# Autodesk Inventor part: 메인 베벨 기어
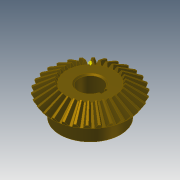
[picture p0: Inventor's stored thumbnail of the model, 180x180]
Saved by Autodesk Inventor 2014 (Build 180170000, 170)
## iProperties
Created: 2014-10
Part Number: 메인 베벨 기어
Material: 강철
Document SubType Name: Modeling
Designer: KYOUNG IL JANG
Categories: <?xml version="1.0" encoding="UTF-16"?> <MemberInstance><Categories><FamilyTemplate><FamilyTemplateParameter ValueType="xs:double" Id="1" ObjectReferenceKey="da
Mass: 269.24 g
Surface Area: 108.837 cm^2
Volume: 34.2981 cm^3
Density: 7.85 g/cm^3
Appearance: Brindle
CustomPartVersion: 1
Company: 한국ATC센터
Author: KYOUNG IL JANG
Revision Number: 1
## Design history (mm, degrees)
node "맨 위 점"
node "메쉬 평면2"
sketch "톱니 본체 스케치"
  geometry: L1 (0, 0)-(28.669, -21.997); L2 (28.669, -21.997)-(31.109, -18.336); L3 (31.109, -18.336)-(0, 0); L4 (30, -20)-(0, 0); L5 (17.219, -13.212)-(18.685, -11.013); L6 (28.669, -21.997)-(17.219, -13.212); L7 (31.109, -18.336)-(18.685, -11.013); L8 (0, -39.387)-(0, 6.564) reference; L9 (0, -20)-(31.109, -20)
  constraints: 16 end point, 4 point on line, 3 perpendicular, 2 collinear, 1 horizontal alignment, 1 vertical alignment
  dimensions: "d0" = 60 diameter of L4.start L8 (= da_de); "d1" = 57.33744 diameter of L1.end L8 (= da_dfe); "d2" = 62.2188 diameter of L2.end L8 (= da_dae); "d3" = 14.4 distance between parallel lines of L2 L5 (= da_b); "d4" = 18.3359 vertical distance of L2.end L1.start (= da_ve)
revolve "톱니 본체" sketch "톱니 본체 스케치" stored, may be unused: angle "d5" = 90 deg
node "시작점"
node "톱니 평면"
sketch "시작 스케치"
  geometry: L1 (0, -23.505)-(0, 10.645) reference; L2 (-0.709, -2.928)-(0.709, -2.928); A1 r 19.188 centre (-19.457, -7.014) between (-0.709, -2.928) and (-3.232, 3.229); A2 r 19.188 centre (19.457, -7.014) between (3.232, 3.229) and (0.709, -2.928); A3 r 57.403 centre (0, -54.083) between (3.232, 3.229) and (-3.232, 3.229); 1 further point
  constraints: 6 point on circle, 3 centre point, 3 symmetric about line, 2 end point, 1 coincident, 1 perpendicular, 1 other
  dimensions: "d7" = 19.18795 radius of A1 (= fd_rr); "d8" = 19.45712 horizontal distance of point (0, -54.083) A1.centre (= fd_x); "d9" = 47.06905 vertical distance of point (0, -54.083) A1.centre (= fd_y); "d57" = 57.40327 radius of A3 (= 0.5 x fd_dva + 0.3 x da_he); "d58" = 51.15527 distance from line of A3.centre L2 (= 0.5 x fd_dva - 1.12 x da_he)
node "끝점"
  node "끝 평면"
sketch "3D 스케치 오른쪽"
  node "Helical Curve Right" dims "d65" = 229.90621 (computed from da_dm, da_delta, da_beta), "d66" = 31.5, "d67" = 60 (= da_de), "d68" = -9.82794 (= -da_delta), "d69" = 8.10972 (computed from fd_loft, da_delta)
node "끝 평면 오른쪽"
sketch "끝 스케치 오른쪽"
  geometry: L1 (0, -41.54)-(0, 13.178) reference; L2 (-0.422, -1.69)-(0.422, -1.69); A1 r 11.427 centre (-11.587, -4.123) between (-0.422, -1.69) and (-1.925, 1.977); A2 r 11.427 centre (11.587, -4.123) between (1.925, 1.977) and (0.422, -1.69); A3 r 34.184 centre (0, -32.153) between (1.925, 1.977) and (-1.925, 1.977); 1 further point
  constraints: 6 point on circle, 3 centre point, 3 symmetric about line, 2 end point, 1 coincident, 1 perpendicular, 1 other
  dimensions: "d70" = 11.58699 horizontal distance of A3.centre A1.centre (computed from fd_x, fd_ratio); "d71" = 28.03028 vertical distance of point (0, -32.153) A1.centre (computed from fd_y, fd_ratio); "d72" = 11.4267 radius of A1 (computed from fd_rr, fd_ratio); "d73" = 30.46369 distance from line of point (0, -32.153) L2 (computed from d58, fd_ratio); "d74" = 34.18446 radius of A3 (computed from d57, fd_ratio)
feature "로프트 오른쪽" sketch "끝 스케치 오른쪽" dims "d75" = 0, "d77" = 0, "d79" = 0, "d80" = 90 deg, "d85" = 20, "d92" = 90 deg, "d93" = 90 deg, "da_teethtype" = 0 [user parameter]
sketch "3D 스케치 왼쪽"
  node "Helical Curve Left" dims "d26" = 229.90621 (computed from da_dm, da_delta, da_beta), "d27" = 8.10972 (computed from fd_loft, da_delta), "d28" = 60 (= da_de), "d29" = -9.82794 (= -da_delta)
node "끝 평면 왼쪽"
sketch "끝 스케치 왼쪽" dims "d56" = 10.3728 (derived)
  geometry: L1 (0, -43.753)-(0, 15.405) reference; L2 (-0.422, -1.678)-(0.422, -1.678); A1 r 11.427 centre (-11.587, -4.111) between (-0.422, -1.678) and (-1.925, 1.988); A2 r 11.427 centre (11.587, -4.111) between (1.925, 1.988) and (0.422, -1.678); A3 r 34.184 centre (0, -32.142) between (1.925, 1.988) and (-1.925, 1.988); 2 further points; 1 other entity
  constraints: 6 point on circle, 3 centre point, 3 symmetric about line, 2 end point, 1 coincident, 2 other
  dimensions: "d30" = 11.4267 radius of A1 (computed from fd_rr, fd_ratio); "d31" = 11.58699 horizontal distance of point (0, -32.142) A1.centre (computed from fd_x, fd_ratio); "d32" = 28.03028 vertical distance of A1.centre point (0, -32.142) (computed from fd_y, fd_ratio); "d61" = 34.18446 radius of A3 (computed from d57, fd_ratio); "d62" = 30.46369 distance from line of point (0, -32.142) L2 (computed from d58, fd_ratio)
feature "로프트 왼쪽" sketch "끝 스케치 왼쪽" dims "d35" = 0, "d37" = 0, "d39" = 0, "d40" = 90 deg, "d84" = 10, "d90" = 90 deg, "d91" = 90 deg, "da_teethtype" = 0 [user parameter]
sketch "본체 스케치"
  geometry: L1 (0, -35.038)-(0, -19.531) reference; L2 (28.669, -21.997)-(17.219, -13.212) reference; L3 (17.219, -13.212)-(0, -13.212); L4 (28.669, -21.997)-(0, -21.997)
  constraints: 4 end point, 2 perpendicular, 2 point on line
revolve "본체 고정" sketch "본체 스케치" stored, may be unused: angle "d46" = 90 deg
feature "피치 지름" dims angle "d47" = 90 deg
sketch "스케치8"
  geometry: C1 r 22.5 at (0, 0); 1 further point
  constraints: 1 centre point, 1 coincident
  dimensions: "d94" = 45 diameter of C1
extrude "돌출1" join sketch "스케치8" distance "d95" = 13; taper "d96" = 0 deg
sketch "스케치9"
  geometry: 1 further point
hole "구멍1" sketch "스케치9" at (0, 0) diameter "d97" = 17; stored, may be unused: countersink angle "d101" = 90 deg, drill point angle "d103" = 118 deg; dims "d98" = 6, "d99" = 4, "d100" = 2, "d102" = 8
sketch "스케치10"
  geometry: L1 (8.124, 2.5)-(10.8, 2.5); L2 (10.8, 2.5)-(10.8, -2.5); L3 (10.8, -2.5)-(8.124, -2.5); A1 r 8.5 centre (0, 0) between (8.124, 2.5) and (8.124, -2.5) reference; 1 further point
  constraints: 6 end point, 2 parallel, 2 point on circle, 1 horizontal, 1 perpendicular
  dimensions: "d104" = 5 distance of L1.end L2.end; "d112" = 19.3 dimension on A1 L2
extrude "돌출2" cut sketch "스케치10" stored distance "d106" = 10; taper "d107" = 0 deg
chamfer "모따기1" distance "d108" = 1; stored, may be unused: second distance "d109" = 2, angle "d110" = 45 deg
fillet "모깎기1" dims "d111" = 2
body "Solid1"
feature "로프트" dims "d17" = 0, "d18" = 90 deg, "d19" = 0, "d20" = 90 deg, "d89" = 0, "da_teethtype" = 0 [user parameter]
pattern_circular "원형 패턴" dims angle "d22" = 360 deg, "d88" = 0, "da_teethtype" = 0 [user parameter]
pattern_circular "원형 패턴 오른쪽" dims angle "d82" = 360 deg, "da_teethtype" = 0 [user parameter]
pattern_circular "원형 패턴 왼쪽" dims angle "d42" = 360 deg, "da_teethtype" = 0 [user parameter]
sketch "끝 스케치"
  geometry: L1 (0, -15.359)-(0, 6.983) reference; L2 (-0.422, -1.69)-(0.422, -1.69); A1 r 11.427 centre (-11.587, -4.123) between (-0.422, -1.69) and (-1.925, 1.977); A2 r 11.427 centre (11.587, -4.123) between (1.925, 1.977) and (0.422, -1.69); A3 r 34.184 centre (0, -32.153) between (1.925, 1.977) and (-1.925, 1.977); 1 further point
  constraints: 6 point on circle, 3 centre point, 3 symmetric about line, 2 end point, 1 coincident, 1 other
  dimensions: "d12" = 11.4267 radius of A1 (computed from fd_rr, fd_ratio); "d15" = 11.58699 horizontal distance of A1.centre point (0, -32.153) (computed from fd_x, fd_ratio); "d16" = 28.03028 vertical distance of A1.centre point (0, -32.153) (computed from fd_y, fd_ratio); "d59" = 34.18446 radius of A3 (computed from d57, fd_ratio); "d60" = 30.46369 distance from line of A3.centre L2 (computed from d58, fd_ratio)
sketch "Sketch6"
  geometry: L1 (30, -20)-(0, 0) reference; L2 (0, -37.8)-(0, 6.3) reference
body "Srf1"
other parameters: "da_b" = 14.4 [user parameter; used in 2 equation terms], "da_de" = 60 [user parameter; used in 4 equation terms], "da_dae" = 62.2188 [user parameter; used in 2 equation terms], "da_dfe" = 57.33744 [user parameter; used in 1 equation term], "da_le" = 36.05551 [user parameter; used in 1 equation term], "da_omega" = 90 deg [user parameter; used in 1 equation term], "da_beta" = 0 [user parameter; used in 2 equation terms], "da_delta" = 9.82794 [user parameter; used in 8 equation terms], "da_alpha" = 20 deg [user parameter; used in 2 equation terms], "da_he" = 4.4 [user parameter; used in 4 equation terms], "da_ve" = 18.3359 [user parameter; used in 1 equation term], "fd_dv" = 108.16654 (computed from da_de, da_delta) [user parameter; used in 1 equation term], "fd_dva" = 112.16654 (computed from da_dae, da_delta) [user parameter; used in 3 equation terms], "fd_dvb" = 101.6433 (computed from fd_dv, da_alpha) [user parameter; used in 2 equation terms], "da_zv" = 540.83269 [user parameter; used in 1 equation term], "fd_loft" = 14.62 (= da_b + 0.05 x da_he) [user parameter; used in 4 equation terms], "fd_ratio" = 5.95514 (computed from da_le, fd_loft) [user parameter; used in 15 equation terms], "fd_rr" = 19.18795 (computed from fd_dd, fd_dvb) [user parameter; used in 6 equation terms], "fd_angle" = 0.29367 (computed from da_zv) [user parameter; used in 4 equation terms], "fd_x1" = 1.58802 (computed from da_dvw, fd_angle) [user parameter; used in 1 equation term], "fd_y1" = 54.05995 (computed from da_dvw, fd_angle) [user parameter; used in 1 equation term], "fd_x2" = 17.8691 (computed from fd_rr, fd_angle2, fd_angle) [user parameter; used in 1 equation term], "fd_y2" = 6.9909 (computed from fd_rr, fd_angle2, fd_angle) [user parameter; used in 1 equation term], "fd_x" = 19.45712 (= fd_x1 + fd_x2) [user parameter; used in 4 equation terms], "fd_y" = 47.06905 (= fd_y1 - fd_y2) [user parameter; used in 4 equation terms], "fd_angle2" = 3.43555 (computed from fd_dvb, fd_dd, da_alpha) [user parameter; used in 2 equation terms], "fd_dd" = 108.64654 (= fd_dva - 0.8 x da_he) [user parameter; used in 2 equation terms], "da_dvw" = 108.16654 [user parameter; used in 2 equation terms], "d11" = 14.62 (= fd_loft), "da_dm" = 48.01848 [user parameter; used in 2 equation terms], "da_x" = 0 [user parameter], "da_m" = 2 [user parameter], "d48" = 0, "d49" = 0, "d50" = 90 deg (= da_omega), "d51" = 6 deg (computed from da_z), "d52" = 0, "d53" = 0, "d54" = 0
